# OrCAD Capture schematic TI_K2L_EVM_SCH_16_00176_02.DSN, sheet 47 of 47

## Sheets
47 PAGE13 : K2L_SOC&FMC SERDES SW2: size C; title: JESD Serdes switch -2
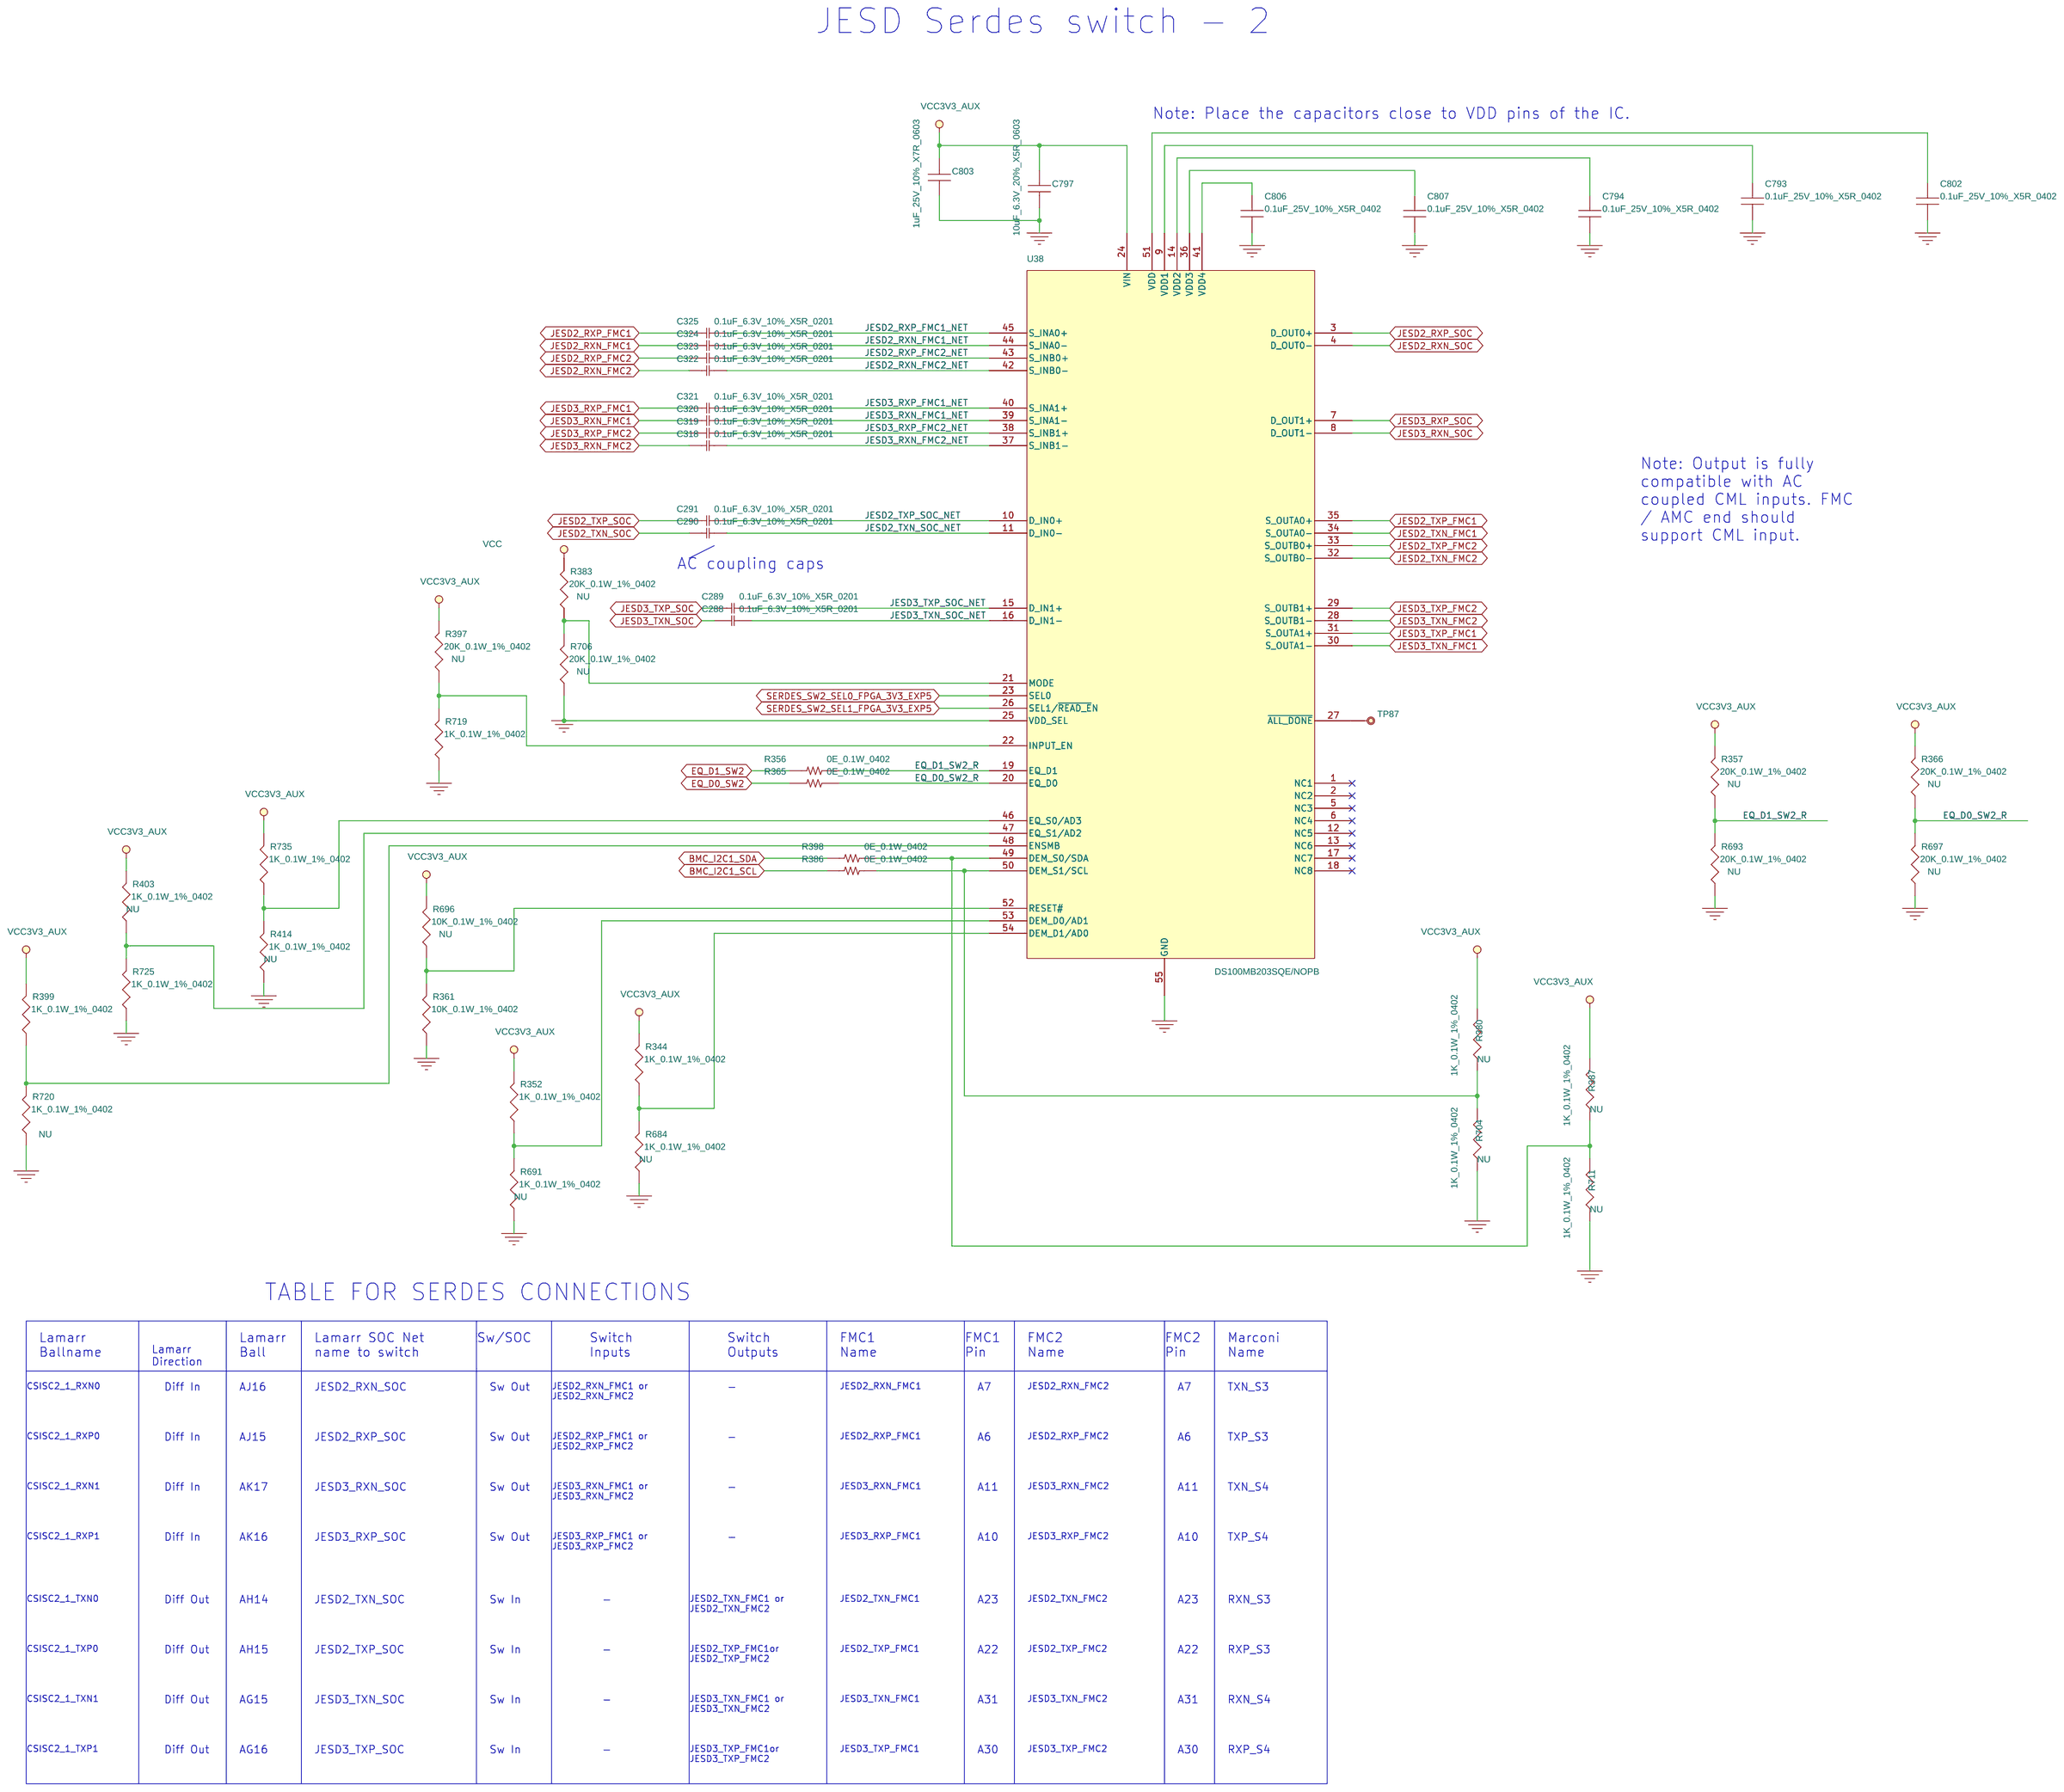
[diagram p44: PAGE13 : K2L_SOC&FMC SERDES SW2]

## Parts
C288  0.1uF_6.3V_10%_X5R_0201  [CC0201]
C289  0.1uF_6.3V_10%_X5R_0201  [CC0201]
C290  0.1uF_6.3V_10%_X5R_0201  [CC0201]
C291  0.1uF_6.3V_10%_X5R_0201  [CC0201]
C318  0.1uF_6.3V_10%_X5R_0201  [CC0201]
C319  0.1uF_6.3V_10%_X5R_0201  [CC0201]
C320  0.1uF_6.3V_10%_X5R_0201  [CC0201]
C321  0.1uF_6.3V_10%_X5R_0201  [CC0201]
C322  0.1uF_6.3V_10%_X5R_0201  [CC0201]
C323  0.1uF_6.3V_10%_X5R_0201  [CC0201]
C324  0.1uF_6.3V_10%_X5R_0201  [CC0201]
C325  0.1uF_6.3V_10%_X5R_0201  [CC0201]
C793  0.1uF_25V_10%_X5R_0402  [C0402]
C794  0.1uF_25V_10%_X5R_0402  [C0402]
C797  10uF_6.3V_20%_X5R_0603  [C0603]
C802  0.1uF_25V_10%_X5R_0402  [C0402]
C803  1uF_25V_10%_X7R_0603  [C0603]
C806  0.1uF_25V_10%_X5R_0402  [C0402]
C807  0.1uF_25V_10%_X5R_0402  [C0402]
R344  1K_0.1W_1%_0402  [R0402]
R352  1K_0.1W_1%_0402  [R0402]
R356  0E_0.1W_0402  [R0402]
R357  20K_0.1W_1%_0402  [RC0402]
R361  10K_0.1W_1%_0402  [R0402]
R365  0E_0.1W_0402  [R0402]
R366  20K_0.1W_1%_0402  [RC0402]
R380  1K_0.1W_1%_0402  [R0402]
R383  20K_0.1W_1%_0402  [RC0402]
R386  0E_0.1W_0402  [R0402]
R387  1K_0.1W_1%_0402  [R0402]
R397  20K_0.1W_1%_0402  [RC0402]
R398  0E_0.1W_0402  [R0402]
R399  1K_0.1W_1%_0402  [R0402]
R403  1K_0.1W_1%_0402  [R0402]
R414  1K_0.1W_1%_0402  [R0402]
R684  1K_0.1W_1%_0402  [R0402]
R691  1K_0.1W_1%_0402  [R0402]
R693  20K_0.1W_1%_0402  [RC0402]
R696  10K_0.1W_1%_0402  [R0402]
R697  20K_0.1W_1%_0402  [RC0402]
R704  1K_0.1W_1%_0402  [R0402]
R706  20K_0.1W_1%_0402  [RC0402]
R711  1K_0.1W_1%_0402  [R0402]
R719  1K_0.1W_1%_0402  [R0402]
R720  1K_0.1W_1%_0402  [R0402]
R725  1K_0.1W_1%_0402  [R0402]
R735  1K_0.1W_1%_0402  [R0402]
TP87  TP  [TP-S40]
U38  DS100MB203SQE/NOPB  [QFN50P550X1000X80-55N_EINF]

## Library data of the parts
C288-C291 C318-C325 = 11_C_12: CAP CER 0.1UF 6.3V 10% X5R 0201; Alt Mfg: Taiyo Yuden; Alt Mfg Part#: TMK105BJ104KV-F; Characteristic: <Characteristic>; Distributor_name: DIGIKEY; Distributor_part_number: 445-1796-1-ND; EIC Part#: 03_00583_01; Manufacture: TDK Corporation; Manufacture Part Number: C0603X5R0J104K030BC; Manufacture(English): TDK Corporation; Manufacture_Part_Number: C0603X5R0J104K030BC; Manufacturer: TDK Corporation; Manufacturer_Part_No: C0603X5R0J104K030BC; Mfg: TDK Corporation; Mfg Part#: 03_00583_01; Mfr_name: TDK Corporation; Mfr_part_number: C0603X5R0J104K030BC; Oper. Temp. Range: -55°C ~ 85°C; Package: 0201; Price @ 1: 0.10000; Price @ 10K: 0.00675; Price @ 1K: 0.00810; ProcessType: SMT; RoHS: Yes; Tolerance: 10%; Vendor: DIGIKEY; Vendor Part#: 445-1796-2-ND; Vendor_Part_No: 445-1796-1-ND; Voltage: 6.3V; eI Part#: 03_00583_01
C793 C794 C802 C806 C807 = CAP: CAP CER 0.1UF 25V 10% X5R 0402; Distributor_name: DIGIKEY; Distributor_part_number: 445-4964-1-ND; EIC Part#: 03_00470_02; Manufacture: TDK Corporation; Manufacture Part Number: C1005X5R1E104K050BC; Manufacture(English): TDK Corporation; Manufacture_Part_Number: GRM155R61E104KA87D; Manufacturer: TDK Corporation; Manufacturer_Part_No: C1005X5R1E104K050BC; Mfg: Murata Electronics North America; Mfg Part#: 03_00470_02; Mfr_name: TDK Corporation; Mfr_part_number: C1005X5R1E104K050BC; Price @ 1: 0.10000; Price @ 1K: 0.00960; Vendor: DIGIKEY; Vendor Part#: 445-4964-1-ND; Vendor_Part_No: 445-4964-1-ND; eI Part#: 03_00470_02
C797 = CAP: CAP CER 10UF 6.3V 20% X5R 0603; Distributor_name: DIGIKEY; Distributor_part_number: 587-3383-1-ND; EIC Part#: 03_00605_01; Manufacture: Taiyo Yuden; Manufacture Part Number: JMK107ABJ106MAHT; Manufacture(English): Taiyo Yuden; Manufacture_Part_Number: JMK107ABJ106MAHT; Manufacturer: Taiyo Yuden; Manufacturer_Part_No: JMK107ABJ106MAHT; Mfg: Taiyo Yuden; Mfg Part#: JMK107ABJ106MAHT; Mfr_name: Taiyo Yuden; Mfr_part_number: JMK107ABJ106MAHT; Price @ 1: 0.44000; Price @ 10K: 0.06105; Price @ 1K: 0.12650; Vendor: DIGIKEY; Vendor_Part_No: 587-3383-1-ND; eI Part#: 03_00605_01
C803 = CAP: CAP CER 1UF 25V 10% X5R 0603; Distributor_name: DIGIKEY; Distributor_part_number: 490-3897-1-ND; EIC Part#: 03_00161_02; Manufacture: Murata; Manufacture Part Number: GRM188R61E105KA12D; Manufacture(English): Murata; Manufacture_Part_Number: GRM188R71E105KA12D; Manufacturer: Murata; Manufacturer_Part_No: GRM188R61E105KA12D; Mfg: Murata; Mfg Part#: 03_00161_02; Mfr_name: Murata; Mfr_part_number: GRM188R61E105KA12D; Price @ 1: 0.38000; Price @ 10K: 0.07363; Price @ 1K: 0.09353; Vendor: DIGIKEY; Vendor_Part_No: 490-3897-1-ND; eI Part#: 03_00161_02
R344 R352 R399 R719 R725 R735 = DISC_RESISTOR: RES 1.00K OHM 1/10W 1% 0402 SMD; Distributor_name: DIGIKEY; Distributor_part_number: P1.00KLCT-ND; EIC Part#: 02_00045_01; Manufacture: Panasonic - ECG; Manufacture Part Number: ERJ-2RKF1001X; Manufacture(English): Panasonic - ECG; Manufacture_Part_Number: ERJ-2RKF1001X; Manufacturer: Panasonic - ECG; Manufacturer_Part_No: ERJ-2RKF1001X; Mfg Part#: 02_00045_01; Mfr_name: Panasonic - ECG; Mfr_part_number: ERJ-2RKF1001X; Price @ 1: 0.10000; Price @ 10K: 0.00347; Price @ 1K: 0.00672; Vendor: DIGIKEY; Vendor_Part_No: P1.00KLCT-ND; eI Part#: 02_00045_01
R356 R365 R386 R398 = 10_R_0: RES 0.0 OHM 1/10W JUMP 0402 SMD; Distributor_name: DIGIKEY; Distributor_part_number: P0.0JCT-ND; EIC Part#: 02_00019_01; Manufacture: Panasonic - ECG; Manufacture Part Number: ERJ-2GE0R00X; Manufacture(English): Panasonic - ECG; Manufacture_Part_Number: ERJ-2GE0R00X; Manufacturer: Panasonic - ECG; Manufacturer_Part_No: ERJ-2GE0R00X; Mfg: PANASONIC ELECTRONIC COMPONENTS (VA); Mfg Part#: 02_00019_01; Mfr_name: Panasonic - ECG; Mfr_part_number: ERJ-2GE0R00X; Price @ 1: 0.05000; Price @ 10K: 0.00248; Price @ 1K: 0.00480; Vendor: DIGIKEY; Vendor_Part_No: P0.0JCT-ND; eI Part#: 02_00019_01
R357 = DISC_RESISTOR: RES 20.0K OHM 1/10W 1% 0402 SMD; Distributor_name: DIGIKEY; Distributor_part_number: P20.0KLCT-ND; EIC Part#: 02_00037_01; Manufacture: Panasonic - ECG; Manufacture Part Number: ERJ-2RKF2002X; Manufacture(English): Panasonic - ECG; Manufacture_Part_Number: ERJ-2RKF2002X; Manufacturer: Panasonic - ECG; Manufacturer_Part_No: ERJ-2RKF2002X; Mfg Part#: 02_00037_01; Mfr_name: Panasonic - ECG; Mfr_part_number: ERJ-2RKF2002X; Mounting Status: NU; Mounting_Status: NU; Price @ 1: 0.10000; Price @ 10K: 0.00347; Price @ 1K: 0.00672; Vendor: DIGIKEY; Vendor_Part_No: P20.0KLCT-ND; eI Part#: 02_00018_05
R361 = DISC_RESISTOR: RES 10K OHM 1/10W 1% 0402 SMD; Distributor_name: DIGIKEY; Distributor_part_number: P10.0KLCT-ND; EIC Part#: 02_00027_01; Manufacture: Panasonic - ECG; Manufacture Part Number: ERJ-2RKF1002X; Manufacture(English): Panasonic - ECG; Manufacture_Part_Number: ERJ-2RKF1002X; Manufacturer: Panasonic - ECG; Manufacturer_Part_No: ERJ-2RKF1002X; Mfg: PANASONIC ELECTRONIC COMPONENTS (VA); Mfg Part#: 02_00027_01; Mfr_name: Panasonic - ECG; Mfr_part_number: ERJ-2RKF1002X; Package: 0402; Price @ 1: 0.10000; Price @ 10K: 0.00347; Price @ 1K: 0.00672; Vendor: DIGIKEY; Vendor_Part_No: P10.0KLCT-ND; eI Part#: 02_00027_01
R366 = DISC_RESISTOR: RES 20.0K OHM 1/10W 1% 0402 SMD; Distributor_name: DIGIKEY; Distributor_part_number: P20.0KLCT-ND; EIC Part#: 02_00037_01; Manufacture: Panasonic - ECG; Manufacture Part Number: ERJ-2RKF2002X; Manufacture(English): Panasonic - ECG; Manufacture_Part_Number: ERJ-2RKF2002X; Manufacturer: Panasonic - ECG; Manufacturer_Part_No: ERJ-2RKF2002X; Mfg Part#: 02_00037_01; Mfr_name: Panasonic - ECG; Mfr_part_number: ERJ-2RKF2002X; Mounting Status: NU; Mounting_Status: NU; Price @ 1: 0.10000; Price @ 10K: 0.00347; Price @ 1K: 0.00672; Vendor: DIGIKEY; Vendor_Part_No: P20.0KLCT-ND; eI Part#: 02_00019_01
R380 R387 R704 R711 = RESISTOR: RES 1.00K OHM 1/10W 1% 0402 SMD; Distributor_name: DIGIKEY; Distributor_part_number: P1.00KLCT-ND; EI Part#: 02_00045_01; EIC Part#: 02_00045_01; Manufacture: Panasonic - ECG; Manufacture Part Number: ERJ-2RKF1001X; Manufacture(English): Panasonic - ECG; Manufacture_Part_Number: ERJ-2RKF1001X; Manufacturer: Panasonic - ECG; Manufacturer_Part_No: ERJ-2RKF1001X; Mfg Part#: 02_00045_01; Mfr_name: Panasonic - ECG; Mfr_part_number: ERJ-2RKF1001X; Mounting Status: NU; Mounting_Status: NU; Price @ 1: 0.10000; Price @ 10K: 0.00347; Price @ 1K: 0.00672; Vendor: DIGIKEY; Vendor_Part_No: P1.00KLCT-ND
R383 = DISC_RESISTOR: RES 20.0K OHM 1/10W 1% 0402 SMD; Distributor_name: DIGIKEY; Distributor_part_number: P20.0KLCT-ND; EIC Part#: 02_00037_01; Manufacture: Panasonic - ECG; Manufacture Part Number: ERJ-2RKF2002X; Manufacture(English): Panasonic - ECG; Manufacture_Part_Number: ERJ-2RKF2002X; Manufacturer: Panasonic - ECG; Manufacturer_Part_No: ERJ-2RKF2002X; Mfg Part#: 02_00037_01; Mfr_name: Panasonic - ECG; Mfr_part_number: ERJ-2RKF2002X; Mounting Status: NU; Mounting_Status: NU; Price @ 1: 0.10000; Price @ 10K: 0.00347; Price @ 1K: 0.00672; Vendor: DIGIKEY; Vendor_Part_No: P20.0KLCT-ND; eI Part#: 02_00348_01
R397 R706 = DISC_RESISTOR: RES 20.0K OHM 1/10W 1% 0402 SMD; Distributor_name: DIGIKEY; Distributor_part_number: P20.0KLCT-ND; EIC Part#: 02_00037_01; Manufacture: Panasonic - ECG; Manufacture Part Number: ERJ-2RKF2002X; Manufacture(English): Panasonic - ECG; Manufacture_Part_Number: ERJ-2RKF2002X; Manufacturer: Panasonic - ECG; Manufacturer_Part_No: ERJ-2RKF2002X; Mfg Part#: 02_00037_01; Mfr_name: Panasonic - ECG; Mfr_part_number: ERJ-2RKF2002X; Mounting Status: NU; Mounting_Status: NU; Price @ 1: 0.10000; Price @ 10K: 0.00347; Price @ 1K: 0.00672; Vendor: DIGIKEY; Vendor_Part_No: P20.0KLCT-ND; eI Part#: 02_00037_01
R403 R414 R684 R691 R720 = DISC_RESISTOR: RES 1.00K OHM 1/10W 1% 0402 SMD; Distributor_name: DIGIKEY; Distributor_part_number: P1.00KLCT-ND; EIC Part#: 02_00045_01; Manufacture: Panasonic - ECG; Manufacture Part Number: ERJ-2RKF1001X; Manufacture(English): Panasonic - ECG; Manufacture_Part_Number: ERJ-2RKF1001X; Manufacturer: Panasonic - ECG; Manufacturer_Part_No: ERJ-2RKF1001X; Mfg Part#: 02_00045_01; Mfr_name: Panasonic - ECG; Mfr_part_number: ERJ-2RKF1001X; Mounting Status: NU; Mounting_Status: NU; Price @ 1: 0.10000; Price @ 10K: 0.00347; Price @ 1K: 0.00672; Vendor: DIGIKEY; Vendor_Part_No: P1.00KLCT-ND; eI Part#: 02_00045_01
R693 = DISC_RESISTOR: RES 20.0K OHM 1/10W 1% 0402 SMD; Distributor_name: DIGIKEY; Distributor_part_number: P20.0KLCT-ND; EIC Part#: 02_00037_01; Manufacture: Panasonic - ECG; Manufacture Part Number: ERJ-2RKF2002X; Manufacture(English): Panasonic - ECG; Manufacture_Part_Number: ERJ-2RKF2002X; Manufacturer: Panasonic - ECG; Manufacturer_Part_No: ERJ-2RKF2002X; Mfg Part#: 02_00037_01; Mfr_name: Panasonic - ECG; Mfr_part_number: ERJ-2RKF2002X; Mounting Status: NU; Mounting_Status: NU; Price @ 1: 0.10000; Price @ 10K: 0.00347; Price @ 1K: 0.00672; Vendor: DIGIKEY; Vendor_Part_No: P20.0KLCT-ND; eI Part#: 02_00968_01
R696 = DISC_RESISTOR: RES 10K OHM 1/10W 1% 0402 SMD; Distributor_name: DIGIKEY; Distributor_part_number: P10.0KLCT-ND; EIC Part#: 02_00027_01; Manufacture: Panasonic - ECG; Manufacture Part Number: ERJ-2RKF1002X; Manufacture(English): Panasonic - ECG; Manufacture_Part_Number: ERJ-2RKF1002X; Manufacturer: Panasonic - ECG; Manufacturer_Part_No: ERJ-2RKF1002X; Mfg Part#: 02_00027_01; Mfr_name: Panasonic - ECG; Mfr_part_number: ERJ-2RKF1002X; Mounting: NU; Mounting Status: NU; Mounting_Status: NU; Package: 0402; Price @ 1: 0.10000; Price @ 10K: 0.00347; Price @ 1K: 0.00672; Vendor: DIGIKEY; Vendor_Part_No: P10.0KLCT-ND; eI Part#: 02_00027_01
R697 = DISC_RESISTOR: RES 20.0K OHM 1/10W 1% 0402 SMD; Distributor_name: DIGIKEY; Distributor_part_number: P20.0KLCT-ND; EIC Part#: 02_00037_01; Manufacture: Panasonic - ECG; Manufacture Part Number: ERJ-2RKF2002X; Manufacture(English): Panasonic - ECG; Manufacture_Part_Number: ERJ-2RKF2002X; Manufacturer: Panasonic - ECG; Manufacturer_Part_No: ERJ-2RKF2002X; Mfg Part#: 02_00037_01; Mfr_name: Panasonic - ECG; Mfr_part_number: ERJ-2RKF2002X; Mounting Status: NU; Mounting_Status: NU; Price @ 1: 0.10000; Price @ 10K: 0.00347; Price @ 1K: 0.00672; Vendor: DIGIKEY; Vendor_Part_No: P20.0KLCT-ND; eI Part#: 02_00806_01
TP87 = 00_TP-S40_0: TEST PAD TP; Distributor_name: NA; Distributor_part_number: NA; EIC Part#: NA; Manufacture: NA; Manufacture Part Number: NA; Manufacture(English): NA; Manufacture_Part_Number: NA; Manufacturer: NA; Manufacturer_Part_No: NA; Mfg: NA; Mfg Part#: NA; Mfr_name: NA; Mfr_part_number: NA; Oper. Temp. Range: --NA--; Package: --NA--; Price @ 1: NA; Price @ 10K: NA; Price @ 1K: NA; ProcessType: SMT; RoHS: Yes; Vendor: NA; Vendor Part#: --NA--; Vendor_Part_No: NA; eI Part#: NA
U38 = DS100MB203SQE: IC MUX/BUFFER DUAL PORT 54WQF; Distributor_name: DIGIKEY; Distributor_part_number: DS100MB203SQE/NOPB-ND; EIC Part#: TBD; Manufacture: TI; Manufacture(English): TI; Manufacturer: TI; Mfg: TI; Mfg Part#: TBD; Mfr_name: TI; Price @ 10K: 14.33300; Price @ 1K: 14.33300; Vendor: DIGIKEY; Vendor_Part_No: DS100MB203SQE/NOPB-ND; eI Part#: 01_01134_01

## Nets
GND: C793.2 C794.2 C797.2 C802.2 C803.1 C806.2 C807.2 R361.1 R414.1 R684.1 R691.1 R693.1 R697.1 R704.2 R706.1 R711.2 R719.1 R720.1 R725.1 U38.25(VDD_SEL) U38.55(GND) ; also on sheet 1 2 3 4 5 6 8 10 11 12 13 14 15 16 17 18 19 20 21 22 24 25 26 27 28 29 33 34 35 36 37 40 41 42 43 45 46
VCC3V3_AUX: C797.1 C803.2 R344.2 R352.2 R357.2 R366.2 R380.1 R383.2 R387.1 R397.2 R399.2 R403.2 R696.2 R735.2 U38.24(VIN) ; also on sheet 2 4 6 8 11 12 13 16 18 19 22 25 26 27 28 29 33 35 37 40 45
BMC_I2C1_SCL: R386.1 ; also on sheet 4 5 40 41 45
BMC_I2C1_SDA: R398.1 ; also on sheet 4 5 40 41 45
EQ_D0_SW2: R365.1 ; also on sheet 45
EQ_D0_SW2_R: R365.2 R366.1 R697.2 U38.20(EQ_D0)
EQ_D1_SW2: R356.1 ; also on sheet 45
EQ_D1_SW2_R: R356.2 R357.1 R693.2 U38.19(EQ_D1)
JESD2_RXN_FMC1: C324.1 ; also on sheet 43
JESD2_RXN_FMC1_NET: C324.2 U38.44(S_INA0-)
JESD2_RXN_FMC2: C322.1 ; also on sheet 46
JESD2_RXN_FMC2_NET: C322.2 U38.42(S_INB0-)
JESD2_RXN_SOC: U38.4(D_OUT0-) ; also on sheet 16
JESD2_RXP_FMC1: C325.1 ; also on sheet 43
JESD2_RXP_FMC1_NET: C325.2 U38.45(S_INA0+)
JESD2_RXP_FMC2: C323.1 ; also on sheet 46
JESD2_RXP_FMC2_NET: C323.2 U38.43(S_INB0+)
JESD2_RXP_SOC: U38.3(D_OUT0+) ; also on sheet 16
JESD2_TXN_FMC1: U38.34(S_OUTA0-) ; also on sheet 43
JESD2_TXN_FMC2: U38.32(S_OUTB0-) ; also on sheet 46
JESD2_TXN_SOC: C290.1 ; also on sheet 16
JESD2_TXN_SOC_NET: C290.2 U38.11(D_IN0-)
JESD2_TXP_FMC1: U38.35(S_OUTA0+) ; also on sheet 43
JESD2_TXP_FMC2: U38.33(S_OUTB0+) ; also on sheet 46
JESD2_TXP_SOC: C291.1 ; also on sheet 16
JESD2_TXP_SOC_NET: C291.2 U38.10(D_IN0+)
JESD3_RXN_FMC1: C320.1 ; also on sheet 43
JESD3_RXN_FMC1_NET: C320.2 U38.39(S_INA1-)
JESD3_RXN_FMC2: C318.1 ; also on sheet 46
JESD3_RXN_FMC2_NET: C318.2 U38.37(S_INB1-)
JESD3_RXN_SOC: U38.8(D_OUT1-) ; also on sheet 16
JESD3_RXP_FMC1: C321.1 ; also on sheet 43
JESD3_RXP_FMC1_NET: C321.2 U38.40(S_INA1+)
JESD3_RXP_FMC2: C319.1 ; also on sheet 46
JESD3_RXP_FMC2_NET: C319.2 U38.38(S_INB1+)
JESD3_RXP_SOC: U38.7(D_OUT1+) ; also on sheet 16
JESD3_TXN_FMC1: U38.30(S_OUTA1-) ; also on sheet 43
JESD3_TXN_FMC2: U38.28(S_OUTB1-) ; also on sheet 46
JESD3_TXN_SOC: C288.1 ; also on sheet 16
JESD3_TXN_SOC_NET: C288.2 U38.16(D_IN1-)
JESD3_TXP_FMC1: U38.31(S_OUTA1+) ; also on sheet 43
JESD3_TXP_FMC2: U38.29(S_OUTB1+) ; also on sheet 46
JESD3_TXP_SOC: C289.1 ; also on sheet 16
JESD3_TXP_SOC_NET: C289.2 U38.15(D_IN1+)
SERDES_SW2_SEL0_FPGA_3V3_EXP5: U38.23(SEL0) ; also on sheet 27
SERDES_SW2_SEL1_FPGA_3V3_EXP5: U38.26(SEL1/~{READ_E}N) ; also on sheet 27
N17487374: C806.1 U38.41(VDD4)
N17487380: C807.1 U38.36(VDD3)
N17487394: C794.1 U38.14(VDD2)
N17487404: C793.1 U38.9(VDD1)
N17487414: C802.1 U38.51(VDD)
N17487463: R383.1 R706.2 U38.21(MODE)
N17487528: R397.1 R719.2 U38.22(INPUT_EN)
N17487549: R399.1 R720.2 U38.48(ENSMB)
N17487590: R414.2 R735.1 U38.46(EQ_S0/AD3)
N17487592: R403.1 R725.2 U38.47(EQ_S1/AD2)
N17487604: R344.1 R684.2 U38.54(DEM_D1/AD0)
N17487637: R352.1 R691.2 U38.53(DEM_D0/AD1)
N17487762: R361.2 R696.1 U38.52(RESET#)
N19610257: R387.2 R398.2 R711.1 U38.49(DEM_S0/SDA)
N19610260: R380.2 R386.2 R704.1 U38.50(DEM_S1/SCL)
N23105689: TP87.1 U38.27(~{ALL_DONE})

Not connected (* = marked no-connect by the designer): U38 1(NC1)* 2(NC2)* 5(NC3)* 6(NC4)* 12(NC5)* 13(NC6)* 17(NC7)* 18(NC8)*

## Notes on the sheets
sheet 47
- JESD Serdes switch - 2
- Note: Place the capacitors close to VDD pins of the IC.
- Note: Output is fully
  compatible with AC
  coupled CML inputs. FMC
  / AMC end should
  support CML input.
- AC coupling caps
- TABLE FOR SERDES CONNECTIONS
- Lamarr
  Ballname
- Lamarr
  Ball
- Lamarr SOC Net
  name to switch
- Sw/SOC
- Switch
  Inputs
- Switch
  Outputs
- FMC1
  Name
- FMC1
  Pin
- FMC2
  Name
- FMC2
  Pin
- Marconi
  Name
- Lamarr
  Direction
- CSISC2_1_RXN0
- Diff In
- AJ16
- JESD2_RXN_SOC
- Sw Out
- JESD2_RXN_FMC1 or
  JESD2_RXN_FMC2
- -
- JESD2_RXN_FMC1
- A7
- JESD2_RXN_FMC2
- A7
- TXN_S3
- CSISC2_1_RXP0
- Diff In
- AJ15
- JESD2_RXP_SOC
- Sw Out
- JESD2_RXP_FMC1 or
  JESD2_RXP_FMC2
- -
- JESD2_RXP_FMC1
- A6
- JESD2_RXP_FMC2
- A6
- TXP_S3
- CSISC2_1_RXN1
- Diff In
- AK17
- JESD3_RXN_SOC
- Sw Out
- JESD3_RXN_FMC1 or
  JESD3_RXN_FMC2
- -
- JESD3_RXN_FMC1
- A11
- JESD3_RXN_FMC2
- A11
- TXN_S4
- CSISC2_1_RXP1
- Diff In
- AK16
- JESD3_RXP_SOC
- Sw Out
- JESD3_RXP_FMC1 or
  JESD3_RXP_FMC2
- -
- JESD3_RXP_FMC1
- A10
- JESD3_RXP_FMC2
- A10
- TXP_S4
- CSISC2_1_TXN0
- Diff Out
- AH14
- JESD2_TXN_SOC
- Sw In
- -
- JESD2_TXN_FMC1 or
  JESD2_TXN_FMC2
- JESD2_TXN_FMC1
- A23
- JESD2_TXN_FMC2
- A23
- RXN_S3
- CSISC2_1_TXP0
- Diff Out
- AH15
- JESD2_TXP_SOC
- Sw In
- -
- JESD2_TXP_FMC1or
  JESD2_TXP_FMC2
- JESD2_TXP_FMC1
- A22
- JESD2_TXP_FMC2
- A22
- RXP_S3
- CSISC2_1_TXN1
- Diff Out
- AG15
- JESD3_TXN_SOC
- Sw In
- -
- JESD3_TXN_FMC1 or
  JESD3_TXN_FMC2
- JESD3_TXN_FMC1
- A31
- JESD3_TXN_FMC2
- A31
- RXN_S4
- CSISC2_1_TXP1
- Diff Out
- AG16
- JESD3_TXP_SOC
- Sw In
- -
- JESD3_TXP_FMC1or
  JESD3_TXP_FMC2
- JESD3_TXP_FMC1
- A30
- JESD3_TXP_FMC2
- A30
- RXP_S4
